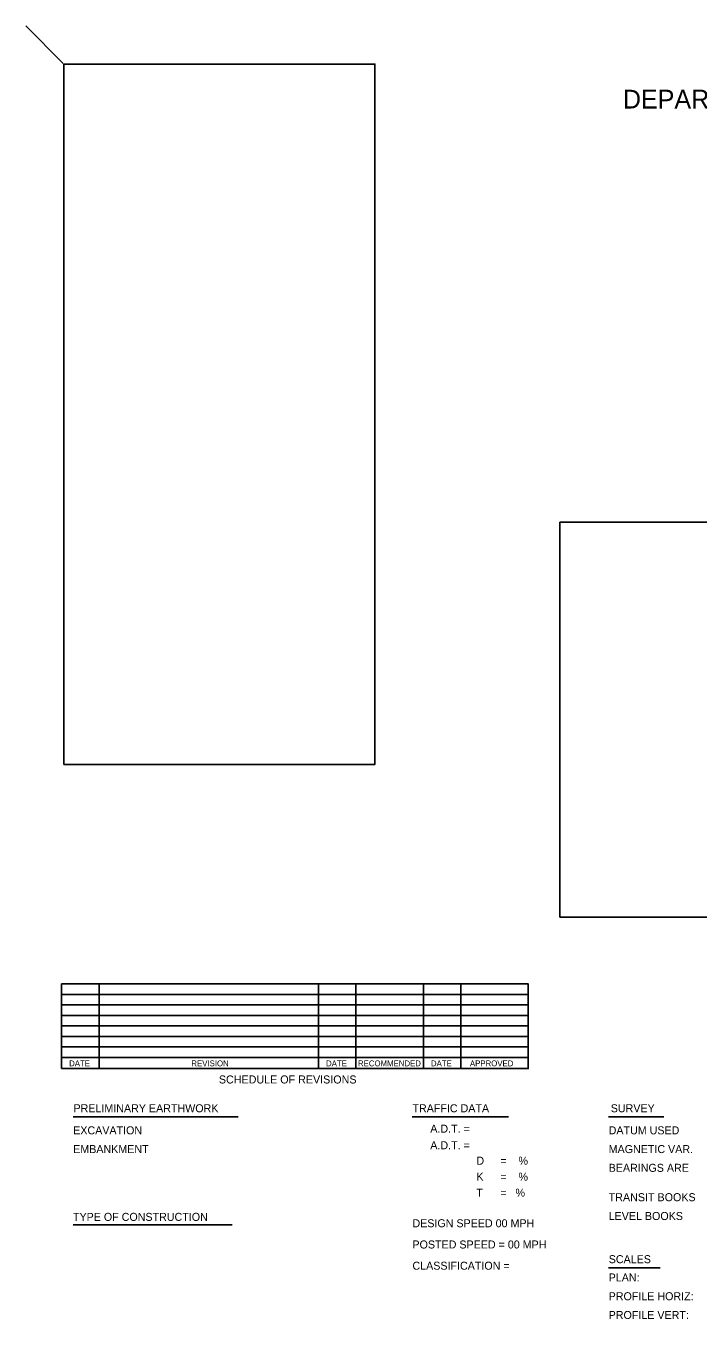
# Model space of a CAD drawing. Extents: x 0.19 to 2.82, y 0.04 to 1.79.
# Drawn here: x 0.191 to 1.088, y 0.067 to 1.792 of the extents above; entities that cross this region are included whole.
import ezdxf

# ---------------------------------------------------------------- set-up
doc = ezdxf.new("R2010")
doc.units = 0
for name, color, linetype in [('Annotation', 7, 'Continuous'), ('Layout Map Info', 7, 'Continuous'), ('Seal', 7, 'Continuous'), ('Standard Info', 7, 'Continuous')]:
    doc.layers.add(name, color=color, linetype=linetype)

msp = doc.modelspace()

# ---------------------------------------------------------------- linework, layer by layer
at = {"layer": 'Annotation'}
msp.add_lwpolyline([(0.242, 0.8071), (0.6569, 0.8071), (0.6569, 1.7408), (0.242, 1.7408)], close=True, dxfattribs=at)
at = {"layer": 'Layout Map Info'}
msp.add_lwpolyline([(0.9038, 0.6035), (2.1045, 0.6035), (2.1045, 1.1298), (0.9038, 1.1298)], close=True, dxfattribs=at)
at = {"layer": 'Seal'}
for p, q in [((0.2543, 0.3371), (0.4744, 0.3371)), ((0.7066, 0.3371), (0.835, 0.3371)), ((0.9688, 0.3371), (1.0424, 0.3371)), ((0.9688, 0.1359), (1.0374, 0.1359))]:
    msp.add_line(p, q, dxfattribs=at)
at = {"layer": 'Standard Info'}
for p, q in [((0.1911, 1.7917), (0.2411, 1.7417)), ((0.2388, 0.5004), (0.5816, 0.5004)), ((0.2888, 0.4014), (0.2888, 0.5144)), ((0.5816, 0.4405), (0.5816, 0.5144)), ((0.5816, 0.4014), (0.5816, 0.5144)), ((0.5816, 0.5004), (0.8616, 0.5004)), ((0.6316, 0.4014), (0.6316, 0.5144)), ((0.7216, 0.4014), (0.7216, 0.5144)), ((0.7716, 0.4014), (0.7716, 0.5144)), ((0.2388, 0.4864), (0.5816, 0.4864)), ((0.5816, 0.4864), (0.8616, 0.4864)), ((0.2388, 0.4724), (0.5816, 0.4724)), ((0.5816, 0.4724), (0.8616, 0.4724)), ((0.2388, 0.4584), (0.5816, 0.4584)), ((0.5816, 0.4584), (0.8616, 0.4584)), ((0.2388, 0.4444), (0.5816, 0.4444)), ((0.5816, 0.4444), (0.8616, 0.4444)), ((0.5816, 0.4014), (0.5816, 0.4405)), ((0.2388, 0.4304), (0.5816, 0.4304)), ((0.2388, 0.4164), (0.5816, 0.4164)), ((0.5816, 0.4304), (0.8616, 0.4304)), ((0.5816, 0.4164), (0.8616, 0.4164)), ((0.2543, 0.1933), (0.4663, 0.1933))]:
    msp.add_line(p, q, dxfattribs=at)
msp.add_lwpolyline([(0.2388, 0.4014), (0.8616, 0.4014), (0.8616, 0.5144), (0.2388, 0.5144)], close=True, dxfattribs=at)

# ---------------------------------------------------------------- texts
for s, height, p in [('DEPARTMENT  OF  TRANSPORTATION  AND  DEVELOPMENT', 0.025, (0.9878, 1.6815)), ('DATE', 0.0078, (0.2489, 0.4045)), ('REVISION', 0.0078, (0.412, 0.4045)), ('DATE', 0.0078, (0.5917, 0.4045)), ('RECOMMENDED', 0.0078, (0.6343, 0.4045)), ('DATE', 0.0078, (0.7317, 0.4045)), ('APPROVED', 0.0078, (0.7837, 0.4045)), ('SCHEDULE OF REVISIONS', 0.0107, (0.4487, 0.3816)), ('PRELIMINARY EARTHWORK', 0.01067, (0.2547, 0.3432)), ('TRAFFIC DATA', 0.01067, (0.707, 0.3432)), ('SURVEY', 0.01067, (0.9716, 0.3432)), ('EXCAVATION                 ', 0.01067, (0.2543, 0.3138)), ('      A.D.T. =        ', 0.01067, (0.707, 0.316)), ('DATUM USED                 ', 0.01067, (0.9688, 0.3138)), ('EMBANKMENT                 ', 0.01067, (0.2543, 0.2888)), ('      A.D.T. =        ', 0.01067, (0.707, 0.2939)), ('MAGNETIC VAR.                 ', 0.01067, (0.9688, 0.2888)), ('D', 0.0107, (0.7923, 0.2733)), ('=    % ', 0.01067, (0.8243, 0.2733)), ('K', 0.0107, (0.7923, 0.252)), ('=    %', 0.01067, (0.8243, 0.252)), ('BEARINGS ARE                 ', 0.01067, (0.9688, 0.2638)), ('=   % ', 0.01067, (0.8243, 0.2307)), ('T', 0.0107, (0.7923, 0.2307)), ('TRANSIT BOOKS                 ', 0.0107, (0.9688, 0.2246)), ('TYPE OF CONSTRUCTION', 0.01067, (0.254, 0.1984)), ('LEVEL BOOKS                 ', 0.01067, (0.9688, 0.1996)), ('DESIGN SPEED 00 MPH', 0.01067, (0.707, 0.1899)), ('POSTED SPEED = 00 MPH', 0.01067, (0.707, 0.1616)), ('CLASSIFICATION =     ', 0.01067, (0.707, 0.1333)), ('SCALES', 0.01067, (0.9689, 0.142)), ('PLAN:                 ', 0.01067, (0.9688, 0.1176)), ('PROFILE HORIZ:                 ', 0.01067, (0.9688, 0.0926)), ('PROFILE VERT:                 ', 0.01067, (0.9688, 0.0676))]:
    msp.add_text(s, height=height, dxfattribs=at).set_placement(p)

doc.saveas('drawing.dxf')
